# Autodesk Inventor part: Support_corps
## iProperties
Shininess: 64.0
Length Units: 11269
Angle Units: 11279
Time Units: 11290
Mass Units: 11283
Length Display Precision: 3
Angle Display Precision: 2
Compacted: True
Part Number: Support_corps
Document SubType Name: Sheet Metal
Created: 2008-02
Material: Acier inoxydable, austénitique
Designer: Pascal
Density: 0.0
Volumn: 0.0
Area: 0.0
PropertySet Name: Model Information
Control State: 0
Master: False
Checked Out: False
Author: Pascal
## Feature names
1. Plaque1
2. Pli1
3. Plaque2
4. Pli2
5. Plaque3
6. Pli3
7. Ouverture1
